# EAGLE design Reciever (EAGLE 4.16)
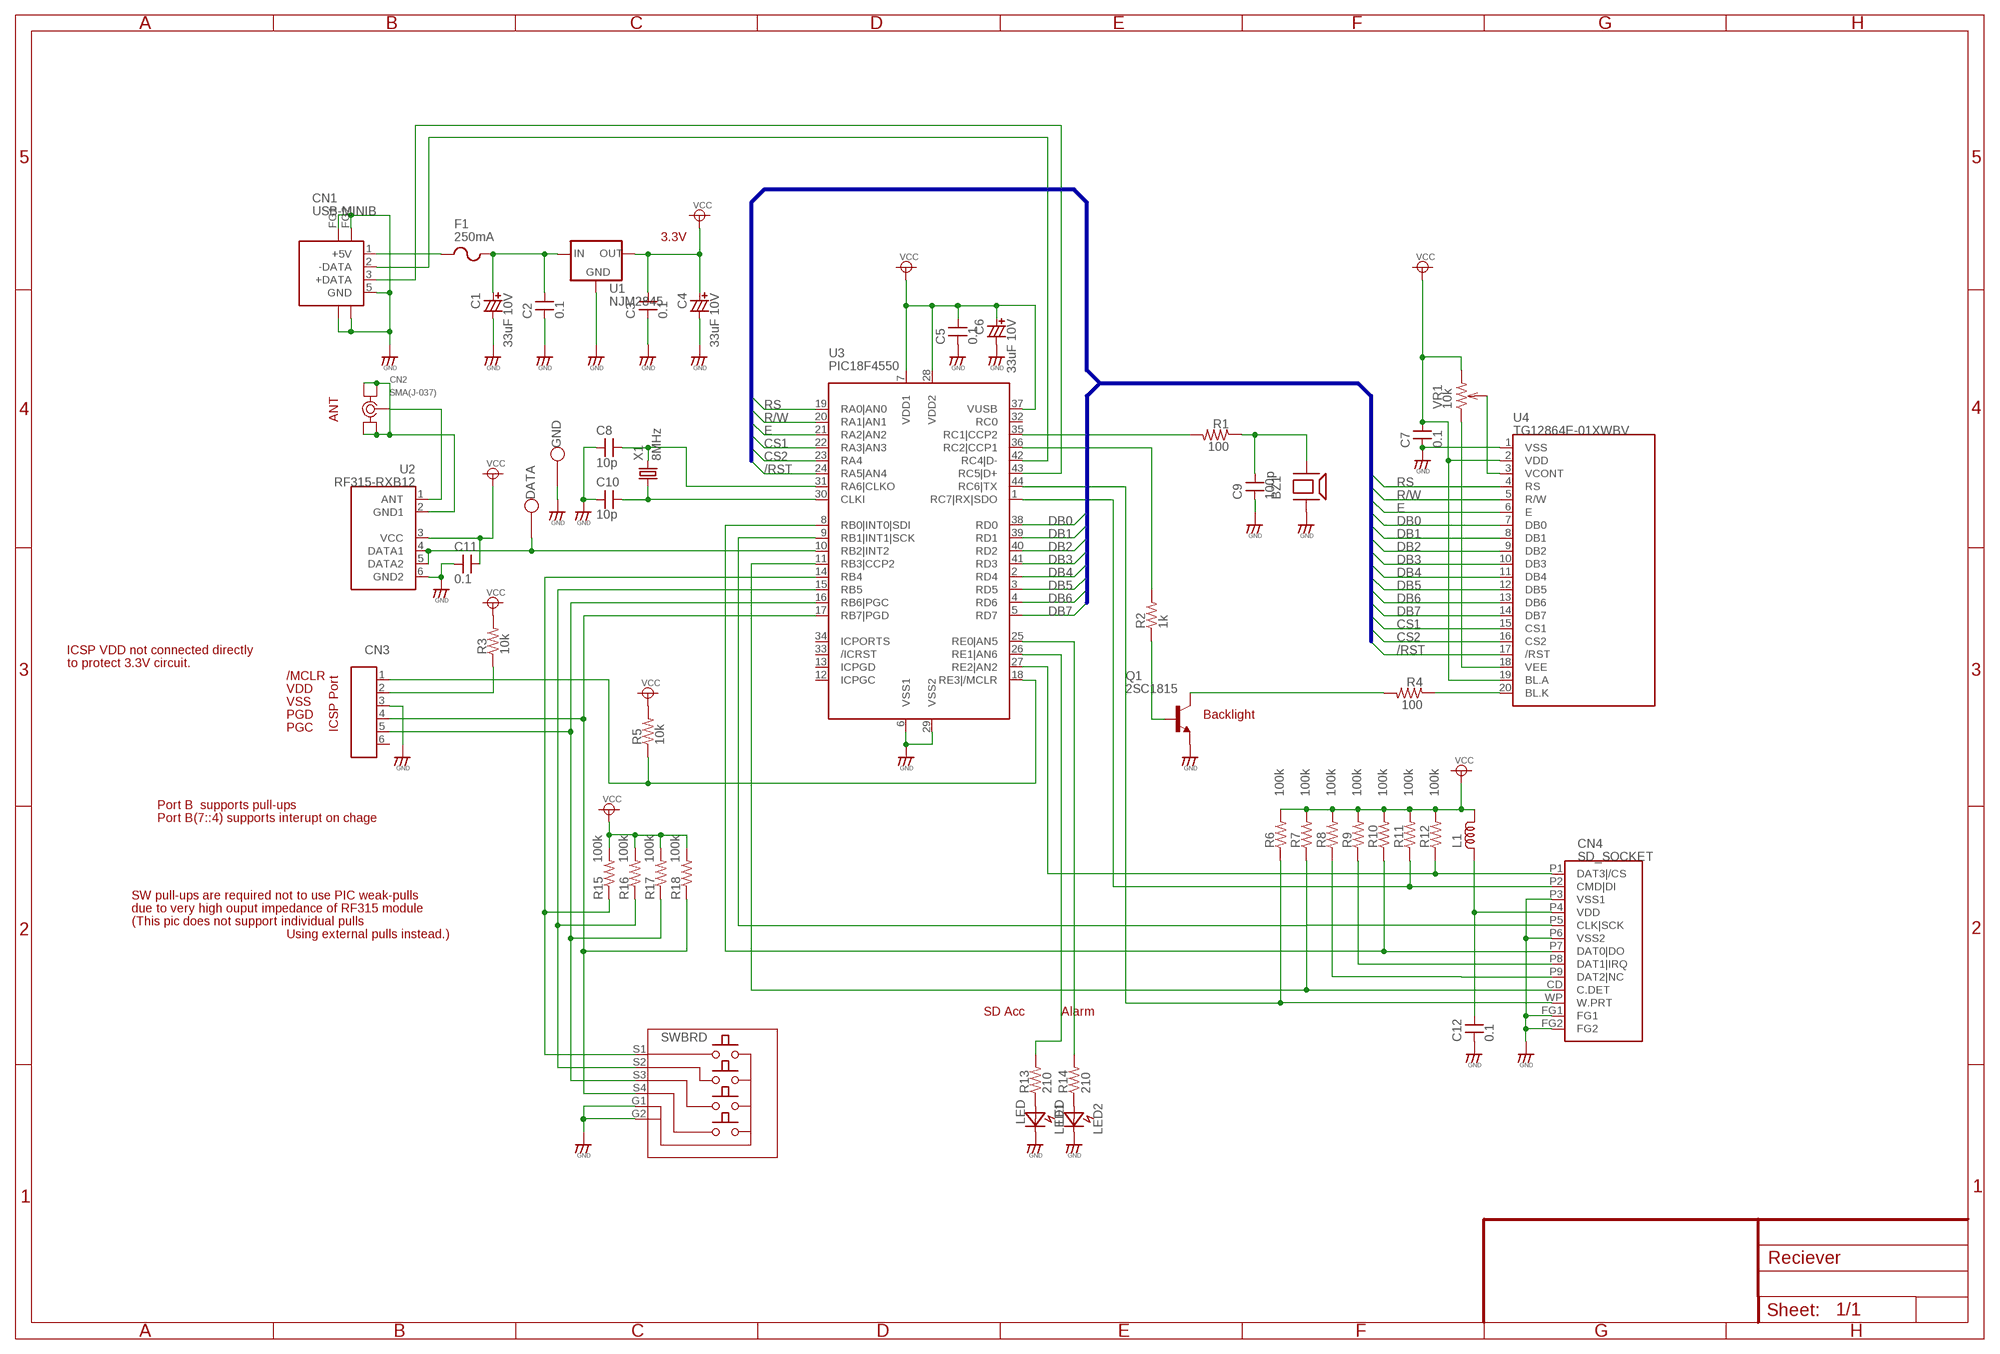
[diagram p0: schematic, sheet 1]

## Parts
BZ1  PIEZO-BZ  [PKM13EPYH4000-A0]
C1  33uF 10V  CCAPSMD3528  [CT3528]
C2  0.1  CAPSM2012  [C2012]
C3  0.1  CAPSM2012  [C2012]
C4  33uF 10V  CCAPSMD3528  [CT3528]
C5  0.1  CAPSM2012  [C2012]
C6  33uF 10V  CCAPSMD3528  [CT3528]
C7  0.1  CAPSM2012  [C2012]
C8  10p  CAPDIP_1  [CAP_DIP_1]
C9  100p  CAPDIP_1  [CAP_DIP_1]
C10  10p  CAPDIP_1  [CAP_DIP_1]
C11  0.1  CAPSM2012  [C2012]
C12  0.1  CAPSM2012  [C2012]
CN1  USB-MINIB  [MINI-USB-B]
CN2  SMA(J-037)  [SMA-J(S-037)]
CN3  CON_6PHDR_L  [CON_HDR_L_SIP6]
CN4  SD_SOCKET  [SD-88]
DATA  TP  [TP]
F1  250mA  POLYSW8X2MM  [AX_08X02_2P_200]
GND  TP  [TP]
L1  MICRO_INDUCTORSMD2012  [L2012C]
LED1  LED  [LED_3MM_VIRT_2]
LED2  LED  [LED_3MM_VIRT_2]
Q1  2SC1815  [TO92]
R1  100  R0.125W_2P  [R_0.125W_2]
R2  1k  RSMD2012  [R2012]
R3  10k  RSMD2012  [R2012]
R4  100  R0.125W_2P  [R_0.125W_2]
R5  10k  RSMD2012  [R2012]
R6  100k  RSMD2012  [R2012]
R7  100k  RSMD2012  [R2012]
R8  100k  RSMD2012  [R2012]
R9  100k  RSMD2012  [R2012]
R10  100k  RSMD2012  [R2012]
R11  100k  RSMD2012  [R2012]
R12  100k  RSMD2012  [R2012]
R13  210  R0.125W_2P  [R_0.125W_2]
R14  210  R0.125W_2P  [R_0.125W_2]
R15  100k  RSMD2012  [R2012]
R16  100k  RSMD2012  [R2012]
R17  100k  RSMD2012  [R2012]
R18  100k  RSMD2012  [R2012]
SWBRD  SW_BOARD  [SW_BOARD]
U1  NJM2845  [TO252]
U2  RF315-RXB12  [RF315-RXB12]
U3  PIC18F4550  [TQFP44]
U4  TG12864E-01XWBV  [TG12864E-01XWBV]
VR1  10k  VR  [VR-7MM]
X1  8MHz  CRYSTALHC49S  [HC49/S]

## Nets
/RST: U3.24(RA5|AN4) U4.17(/RST)
CS1: U3.22(RA3|AN3) U4.15(CS1)
CS2: U3.23(RA4) U4.16(CS2)
DB0: U3.38(RD0) U4.7(DB0)
DB1: U3.39(RD1) U4.8(DB1)
DB2: U3.40(RD2) U4.9(DB2)
DB3: U3.41(RD3) U4.10(DB3)
DB4: U3.2(RD4) U4.11(DB4)
DB5: U3.3(RD5) U4.12(DB5)
DB6: U3.4(RD6) U4.13(DB6)
DB7: U3.5(RD7) U4.14(DB7)
DVCC: C3.2 C4.+ C5.2 C6.+ C7.2 C11.2 L1.2 R3.2 R5.2 R6.2 R7.2 R8.2 R9.2 R10.2 R11.2 R12.2 R15.2 R16.2 R17.2 R18.2 U1.3(OUT) U2.3(VCC) U3.7(VDD1) U3.28(VDD2) U3.37(VUSB) U4.2(VDD) U4.19(BL.A) VR1.3 ; supply symbol labelled VCC
E: U3.21(RA2|AN2) U4.6(E)
GND: BZ1.2 C1.- C2.1 C3.1 C4.- C5.1 C6.- C7.1 C8.1 C9.1 C10.1 C11.1 C12.1 CN1.5(GND) CN1.FG1 CN1.FG2 CN1.FG3 CN1.FG4 CN3.3 CN4.FG1 CN4.FG2 CN4.P3(VSS1) CN4.P6(VSS2) GND.TP LED1.K LED2.K Q1.1(E) SWBRD.G1 SWBRD.G2 U1.2(GND) U2.6(GND2) U3.6(VSS1) U3.29(VSS2) U4.1(VSS)
N$1: CN3.1 R5.1 U3.18(RE3|/MCLR)
N$4: CN1.2(-DATA) U3.42(RC4|D-)
N$5: CN1.3(+DATA) U3.43(RC5|D+)
N$6: R14.2 U3.25(RE0|AN5)
N$8: R2.2 U3.36(RC2|CCP1)
N$9: R4.1 U4.20(BL.K)
N$10: Q1.2(C) R4.2
N$11: DATA.TP U2.4(DATA1) U2.5(DATA2) U3.10(RB2|INT2)
N$12: CN4.P1(DAT3|/CS) R12.1 U3.27(RE2|AN2)
N$13: LED2.A R14.1
N$14: LED1.A R13.1
N$15: CN4.P7(DAT0|DO) R10.1 U3.8(RB0|INT0|SDI)
N$16: CN4.P5(CLK|SCK) U3.9(RB1|INT1|SCK)
N$17: CN4.P2(CMD|DI) R11.1 U3.1(RC7|RX|SDO)
N$18: C1.+ C2.2 F1.2 U1.1(IN)
N$19: CN4.CD(C.DET) R7.1 U3.11(RB3|CCP2)
N$20: CN4.WP(W.PRT) R6.1 U3.44(RC6|TX)
N$21: U4.3(VCONT) VR1.2
N$22: Q1.3(B) R2.1
N$23: CN2.HOT U2.1(ANT)
N$24: C12.2 CN4.P4(VDD) L1.1
N$25: U4.18(VEE) VR1.1
N$27: CN3.2 R3.1
N$28: R13.2 U3.26(RE1|AN6)
N$29: R1.2 U3.35(RC1|CCP2)
N$30: C8.2 U3.31(RA6|CLKO) X1.2
N$31: C10.2 U3.30(CLKI) X1.1
N$32: BZ1.1 C9.2 R1.1
N$33: CN2.G1 CN2.G2 CN2.G3 CN2.G4 U2.2(GND1)
N$34: CN1.1(+5V) F1.1
N$35: R15.1 SWBRD.S1 U3.14(RB4)
N$36: CN4.P8(DAT1|IRQ) R9.1
N$37: CN4.P9(DAT2|NC) R8.1
N$38: R16.1 SWBRD.S2 U3.15(RB5)
N$39: CN3.5 R17.1 SWBRD.S3 U3.16(RB6|PGC)
N$40: CN3.4 R18.1 SWBRD.S4 U3.17(RB7|PGD)
R/W: U3.20(RA1|AN1) U4.5(R/W)
RS: U3.19(RA0|AN0) U4.4(RS)
Unconnected: CN3.6 U3.12(ICPGC) U3.13(ICPGD) U3.32(RC0) U3.33(/ICRST) U3.34(ICPORTS)

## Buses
RS,R/W,E,DB[0..7],CS1,CS2,/RST

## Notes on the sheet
- 3.3V
- ANT
- ICSP VDD not connected directly
- to protect 3.3V circuit.
- /MCLR
- VDD
- VSS
- PGD | Backlight
- PGC | ICSP Port
- Port B  supports pull-ups
- Port B(7::4) supports interupt on chage
- SW pull-ups are required not to use PIC weak-pulls
- due to very high ouput impedance of RF315 module
- (This pic does not support individual pulls
- Using external pulls instead.)
- SD Acc | Alarm

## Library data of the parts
BZ1 = WirelessTemp:PIEZO-BZ
C1 C4 C6 = WirelessTemp:CCAP: Polar capacitor
C2 C3 C5 C7-C12 = WirelessTemp:CAP: Non polar capacitor
CN1 = WirelessTemp:USB-MINIB
CN2 = WirelessTemp:SMA(J-037)
CN3 = WirelessTemp:CON_6P
CN4 = WirelessTemp:SD_SOCKET
DATA GND = WirelessTemp:TP
F1 = WirelessTemp:POLYSW
L1 = WirelessTemp:MICRO_INDUCTOR
LED1 LED2 = WirelessTemp:LED
Q1 = WirelessTemp:2SC1815: General use NPN transistor
R1-R18 = WirelessTemp:R
SWBRD = WirelessTemp:SW_BOARD
U1 = WirelessTemp:NJM2845
U2 = WirelessTemp:RF315-RXB12
U3 = WirelessTemp:PIC18F4550
U4 = WirelessTemp:TG12864E-01XWBV
VR1 = WirelessTemp:VR
X1 = WirelessTemp:CRYSTAL: CRYSTAL

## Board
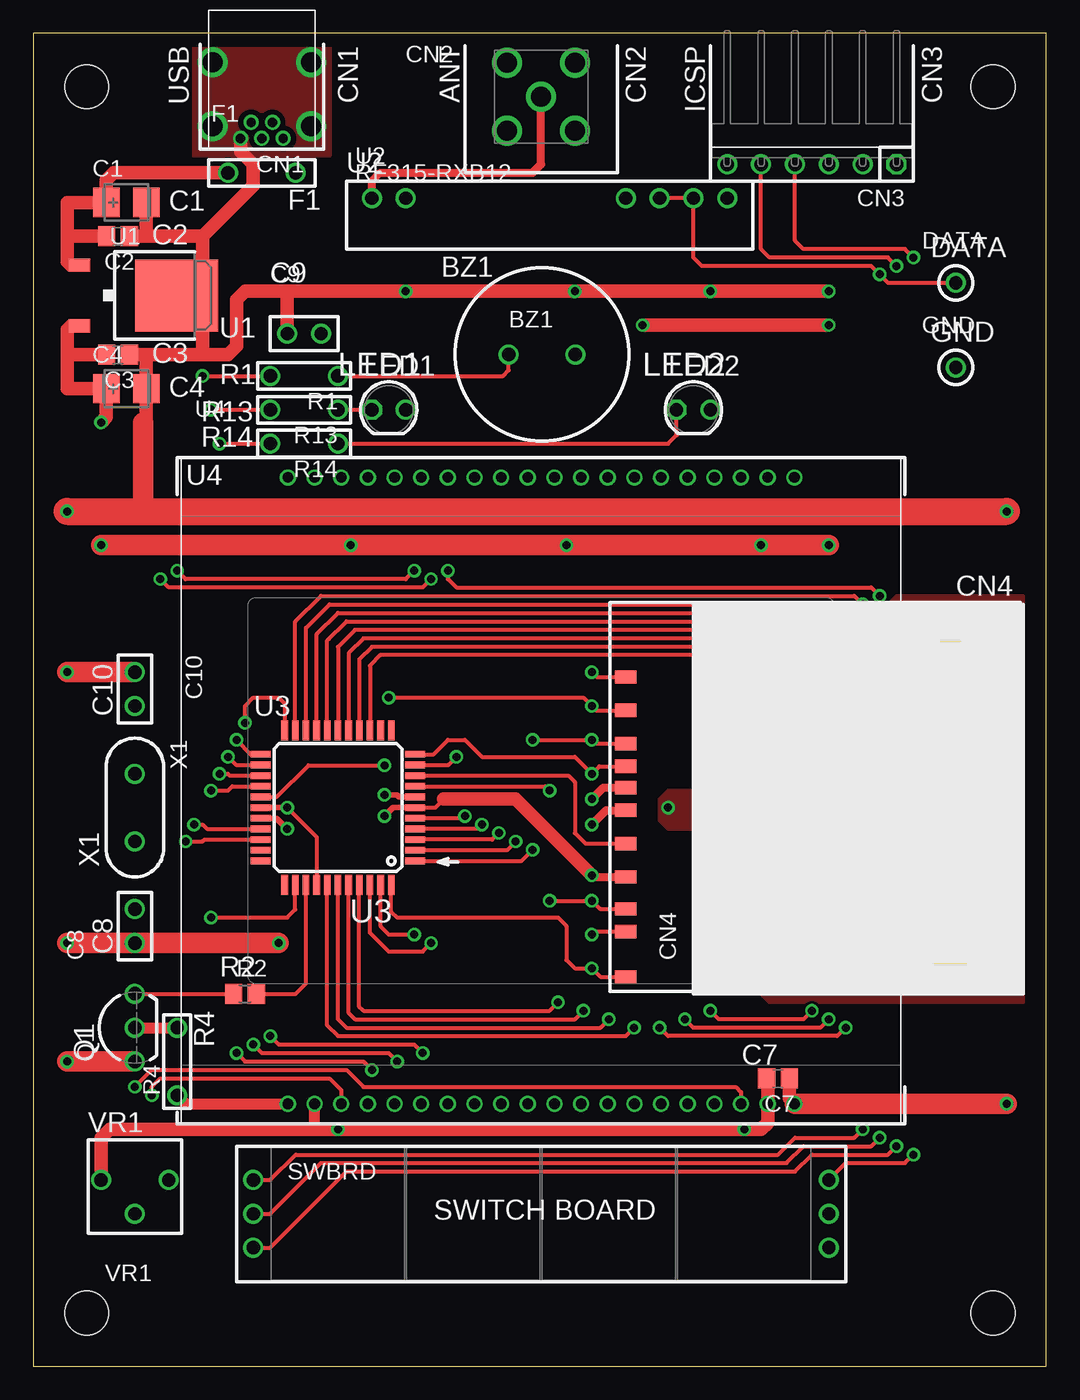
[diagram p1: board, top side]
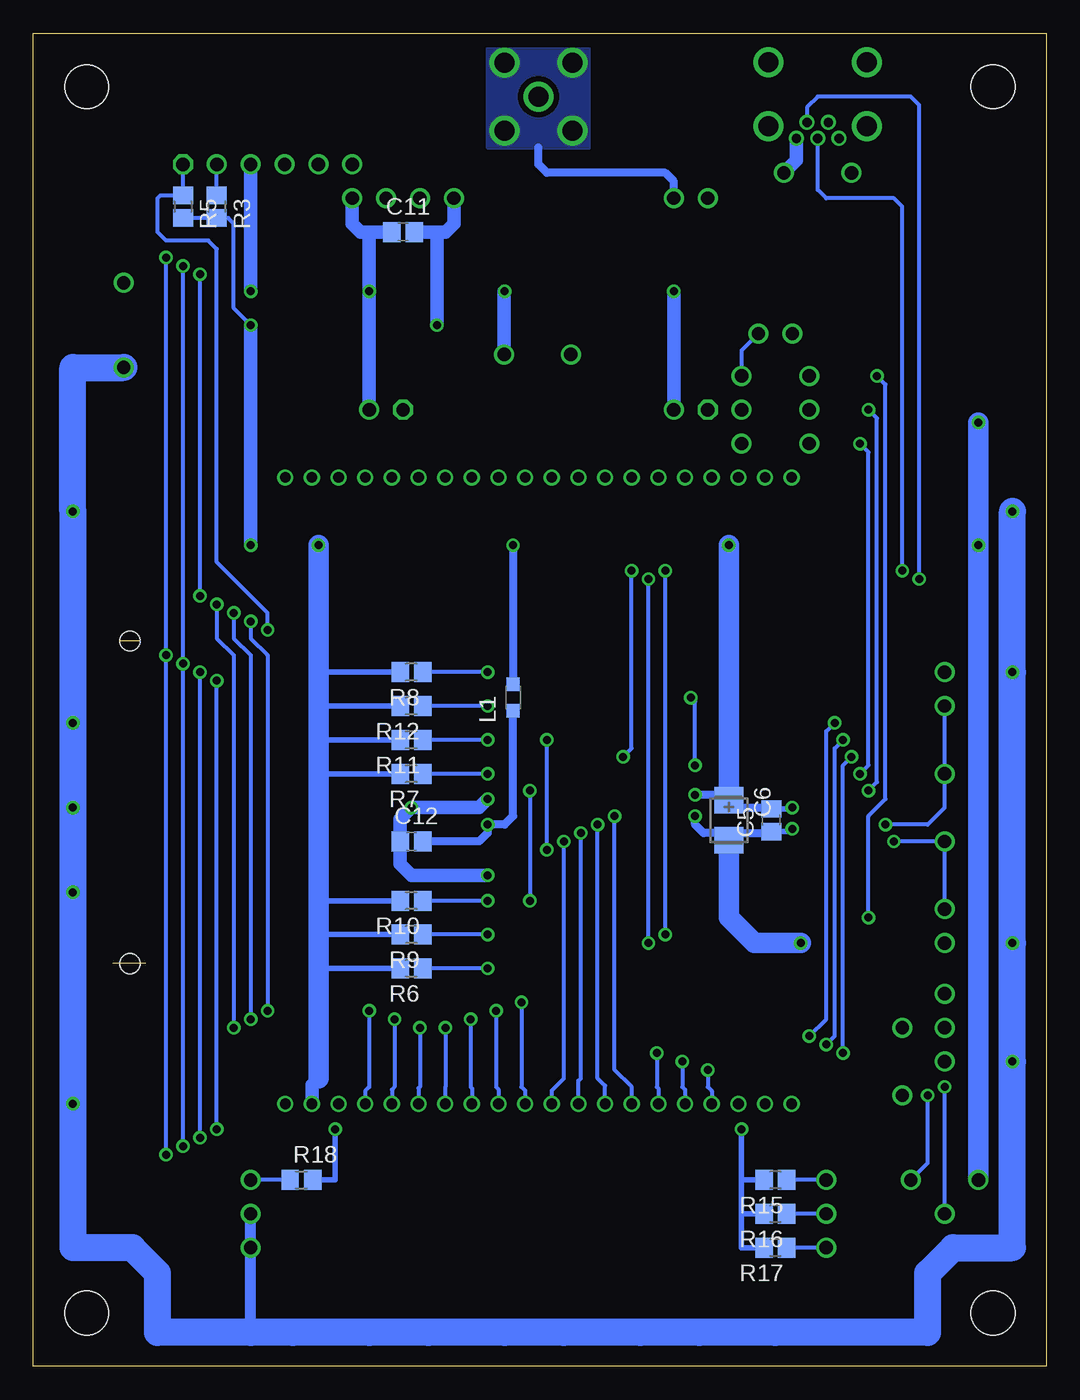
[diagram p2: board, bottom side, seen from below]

Size 76 x 100 mm. Coordinates in mm from the lower left corner, seen from the top.
Outline: 0,0 76,0 76,100 0,100 0,0
Copper layers (1*16): Top 0.035mm / dielectric 1.5mm / Bottom 0.035mm
Design rules "Olimex8mils": minimum track width 8mil, minimum drill 0.6mm, track to track 8mil, track to pad 8mil, pad to pad 8mil, via to via 8mil, smd to smd 8mil, copper to edge 40mil, drill to drill 10mil, minimum pad ring 8mil, minimum via ring 8mil, stop-mask expansion 0mil, vias tented up to drill 0mil, thermal gap 10mil
Holes 3.3 mm at 4,96 72,96 72,4 4,4

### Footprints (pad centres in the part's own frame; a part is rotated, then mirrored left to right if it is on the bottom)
PKM13EPYH4000-A0 = drill 1 round: 1 -2.5,0; 2 2.5,0
CT3528 = smd 2 x 2.2: + -1.5,0; - 1.5,0
C2012 = smd 1.3 x 1.5: 1 -0.85,0; 2 0.85,0
CAP_DIP_1 = drill 1 round: 1 -1.27,0; 2 1.27,0
MINI-USB-B = drill 0.7 pad 1.118 round: 1 -1.6,4.4; 2 -0.8,3.2; 3 0,4.4; 4 0.8,3.2; 5 1.6,4.4 | drill 1.5 round: FG1 -3.7,3.5; FG2 3.7,3.5; FG3 -3.7,-1.3; FG4 3.7,-1.3
SMA-J(S-037) = drill 1.5 round: G1 -2.54,2.54; G2 2.54,2.54; G3 -2.54,-2.54; G4 2.54,-2.54; HOT 0,0
CON_HDR_L_SIP6 = drill 1 octagon: 1 -6.35,0 | drill 1 round: 2 -3.81,0; 3 -1.27,0; 4 1.27,0; 5 3.81,0; 6 6.35,0
SD-88 = smd 1 x 1.6: CD 15.8,0; P1 20,0; P2 17.5,0; P3 14.2,0; P4 12.5,0; P5 10,0; P6 7.5,0; P7 5.1,0; P8 3.4,0; P9 22.5,0; WP 0,0 | smd 1.2 x 1.6: FG1 27.5,-21; FG2 -0.5,-22.2 | hole 1.5: 1,-24.3; 25.2,-24.3
TP = drill 1 round: TP 0,0
AX_08X02_2P_200 = drill 1 round: 1 2.54,0; 2 -2.54,0
L2012C = smd 1 x 1: 1 -1,0; 2 1,0
LED_3MM_VIRT_2 = drill 1 octagon: A -1.27,0 | drill 1 round: K 1.27,0
TO92 = drill 1 round: 1 -2.54,0; 2 0,0; 3 2.54,0
R_0.125W_2 = drill 1 round: 1 -2.54,0; 2 2.54,0
R2012 = smd 1.3 x 1.5: 1 -0.85,0; 2 0.85,0
SW_BOARD = drill 1 round: G1 21.59,0; G2 21.59,-2.54; S1 -21.59,2.54; S2 -21.59,0; S3 -21.59,-2.54; S4 21.59,2.54
TO252 = smd 1 x 1.6: 1 -2.28,-4.8; 3 2.28,-4.8 | smd 5.4 x 6.2: 2 0,2.5
RF315-RXB12 = drill 1 round: 1 -12.7,0; 2 -10.16,0; 3 6.35,0; 4 8.89,0; 5 11.43,0; 6 13.97,0
TQFP44 = smd 1.5 x 0.5: 1 -5.8,4; 2 -5.8,3.2; 3 -5.8,2.4; 4 -5.8,1.6; 5 -5.8,0.8; 6 -5.8,0; 7 -5.8,-0.8; 8 -5.8,-1.6; 9 -5.8,-2.4; 10 -5.8,-3.2; 11 -5.8,-4; 23 5.8,-4; 24 5.8,-3.2; 25 5.8,-2.4; 26 5.8,-1.6; 27 5.8,-0.8; 28 5.8,0; 29 5.8,0.8; 30 5.8,1.6; 31 5.8,2.4; 32 5.8,3.2; 33 5.8,4 | smd 0.5 x 1.5: 12 -4,-5.8; 13 -3.2,-5.8; 14 -2.4,-5.8; 15 -1.6,-5.8; 16 -0.8,-5.8; 17 0,-5.8; 18 0.8,-5.8; 19 1.6,-5.8; 20 2.4,-5.8; 21 3.2,-5.8; 22 4,-5.8; 34 4,5.8; 35 3.2,5.8; 36 2.4,5.8; 37 1.6,5.8; 38 0.8,5.8; 39 0,5.8; 40 -0.8,5.8; 41 -1.6,5.8; 42 -2.4,5.8; 43 -3.2,5.8; 44 -4,5.8
TG12864E-01XWBV = drill 0.8 round: 1 19,-23.5; 2 17,-23.5; 3 15,-23.5; 4 13,-23.5; 5 11,-23.5; 6 9,-23.5; 7 7,-23.5; 8 5,-23.5; 9 3,-23.5; 10 1,-23.5; 11 -1,-23.5; 12 -3,-23.5; 13 -5,-23.5; 14 -7,-23.5; 15 -9,-23.5; 16 -11,-23.5; 17 -13,-23.5; 18 -15,-23.5; 19 -17,-23.5; 20 -19,-23.5; 21 19,23.5; 22 17,23.5; 23 15,23.5; 24 13,23.5; 25 11,23.5; 26 9,23.5; 27 7,23.5; 28 5,23.5; 29 3,23.5; 30 1,23.5; 31 -1,23.5; 32 -3,23.5; 33 -5,23.5; 34 -7,23.5; 35 -9,23.5; 36 -11,23.5; 37 -13,23.5; 38 -15,23.5; 39 -17,23.5; 40 -19,23.5
VR-7MM = drill 1 round: 1 -2.54,0; 2 0,2.54; 3 2.54,0
HC49/S = drill 1 round: 1 -2.54,0; 2 2.54,0

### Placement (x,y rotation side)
BZ1  38.16,75.91 0 top
C1  6.99,87.31 0 top
C2  6.35,84.77 180 top
C3  6.35,75.88 180 top
C4  6.99,73.34 0 top
C5  20.64,40.96 90 bottom
C6  23.81,40.96 270 bottom
C7  55.88,21.59 180 top
C8  7.62,33.02 90 top
C9  20.32,77.47 0 top
C10  7.62,50.8 270 top
C11  48.26,85.09 0 bottom
C12  47.62,39.37 0 bottom
CN1  17.14,96.52 180 top
CN2  38.1,95.25 0 top
CN3  58.42,90.17 180 top
CN4  44.45,29.21 90 top
DATA  69.22,81.28 0 top
F1  17.14,89.53 0 top
GND  69.22,74.93 0 top
L1  40.01,50.16 90 bottom
LED1  26.67,71.75 0 top
LED2  49.53,71.75 0 top
Q1  7.62,25.4 90 top
R1  20.32,74.3 180 top
R2  15.88,27.94 0 top
R3  62.23,87 270 bottom
R4  10.79,22.86 90 top
R5  64.77,87 270 bottom
R6  47.62,29.84 180 bottom
R7  47.62,44.45 180 bottom
R8  47.62,52.07 180 bottom
R9  47.62,32.38 180 bottom
R10  47.62,34.92 180 bottom
R11  47.62,46.99 180 bottom
R12  47.62,49.53 180 bottom
R13  20.32,71.75 180 top
R14  20.32,69.22 180 top
R15  20.32,13.97 180 bottom
R16  20.32,11.43 180 bottom
R17  20.32,8.89 180 bottom
R18  55.88,13.97 0 bottom
SWBRD  38.1,11.43 0 top
U1  8.26,80.33 270 top
U2  38.1,87.63 0 top
U3  22.86,41.91 180 top
U4  38.1,43.18 0 top
VR1  7.62,13.97 180 top
X1  7.62,41.91 270 top

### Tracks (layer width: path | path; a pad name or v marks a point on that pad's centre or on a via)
/RST  (via drill 0.6)
  Top 0.305: v15.24,23.5 15.88,22.86 24.77,22.86 v25.4,22.23 | U3.24 15.21,45.11 v14.61,45.72
  Bottom 0.305: v15.24,23.5 15.24,45.09 v14.61,45.72 | v25.4,22.23 25.4,20.95 25.1,20.66 U4.17
CS1  (via drill 0.6)
  Top 0.305: U3.22 18.86,49.72 18.41,50.16 16.51,50.16 15.88,49.53 v15.88,48.26 | v17.78,24.77 18.41,24.13 28.57,24.13 v29.21,23.5
  Bottom 0.305: v17.78,24.77 16.51,26.04 16.51,47.62 v15.88,48.26 | v29.21,23.5 29.21,20.95 29.1,20.84 U4.15
CS2  (via drill 0.6)
  Top 0.305: v16.51,24.13 17.14,23.5 26.67,23.5 v27.3,22.86 | U3.23 16.32,45.91 v15.24,46.99
  Bottom 0.305: v16.51,24.13 15.88,24.77 15.88,46.35 v15.24,46.99 | v27.3,22.86 27.3,20.95 27.1,20.75 U4.16
DB0  (via drill 0.6)
  Top 0.305: v45.09,25.4 44.45,24.77 22.86,24.77 22.06,25.57 U3.38
  Bottom 0.305: v45.09,25.4 45.09,20.95 45.1,20.94 U4.7
DB1  (via drill 0.6)
  Top 0.305: v43.18,26.04 42.55,25.4 23.5,25.4 22.86,26.04 U3.39
  Bottom 0.305: v43.18,26.04 43.18,20.95 43.1,20.88 U4.8
DB2  (via drill 0.6)
  Top 0.305: v41.27,26.67 40.64,26.04 24.13,26.04 23.66,26.5 U3.40
  Bottom 0.305: v41.27,26.67 41.27,20.95 41.1,20.78 U4.9
DB3  (via drill 0.6)
  Top 0.305: v39.37,27.3 38.73,26.67 24.77,26.67 24.46,26.98 U3.41
  Bottom 0.305: v39.37,27.3 39.37,20.95 39.1,20.68 U4.10
DB4  (via drill 0.6)
  Top 0.305: U3.2 35.53,38.71 v36.2,39.37
  Bottom 0.305: v36.2,39.37 36.2,21.59 37.1,20.68 U4.11
DB5  (via drill 0.6)
  Top 0.305: U3.3 34.43,39.51 v34.92,40.01
  Bottom 0.305: v34.92,40.01 34.92,21.59 35.1,21.41 U4.12
DB6  (via drill 0.6)
  Top 0.305: U3.4 33.33,40.31 v33.66,40.64
  Bottom 0.305: v33.66,40.64 33.66,21.59 33.1,21.04 U4.13
DB7  (via drill 0.6)
  Top 0.305: U3.5 32.22,41.11 v32.38,41.27
  Bottom 0.305: v32.38,41.27 32.38,22.23 31.1,20.94 U4.14
DVCC  (via drill 0.6)
  Top 0.305: U3.37 21.26,39.7 v19.05,41.91
  Top 0.406: v19.05,41.91 U3.28 | U3.7 27.46,42.71 27.3,42.86 v26.35,42.86 | C7.2 55.24,21.59 55.1,21.45 | 20.95,17.78 21.1,17.93
  Top 0.813: 21.1,17.93 U4.19
  Top 1.016: 2.54,75.88 2.54,77.79 2.8,78.05 U1.3 | 2.54,75.88 2.54,73.34 C4.+ 5.49,71.21 v5.08,70.8 | 2.54,75.88 C3.2 | 55.1,21.45 U4.2 55.1,18.27 54.61,17.78 v53.34,17.78 v22.86,17.78 20.95,17.78 5.71,17.78 5.08,17.14 VR1.3 | v59.69,78.11 v45.72,78.11
  Top 1.524: v5.08,61.59 v23.81,61.59 v40.01,61.59 v54.61,61.59 v59.69,61.59
  Bottom 0.305: R5.2 R3.2 61.38,86.14 60.96,85.72 60.96,79.38 v59.69,78.11
  Bottom 0.406: C5.2 19.15,41.81 v19.05,41.91 | 54.61,29.84 R6.2 | 54.61,52.07 R8.2 | 54.61,49.53 R12.2 | 54.61,46.99 R11.2 | 54.61,44.45 R7.2 | 54.61,34.92 R10.2 | 54.61,32.38 R9.2 | 22.86,13.97 R15.2 | 22.86,11.43 R16.2 | 22.86,11.43 22.86,8.89 R17.2 | 22.86,13.97 22.86,11.43 | v22.86,17.78 22.86,13.97 | R18.2 53.34,13.97 v53.34,17.78
  Bottom 0.61: v40.01,61.59 L1.2 | v26.35,42.86 24.22,42.86 C6.+ 23.27,41.91 20.74,41.91
  Bottom 0.813: 20.74,41.91 C5.2
  Bottom 1.016: U4.2 55.1,21.1 54.61,21.59 | 45.72,85.09 45.09,85.09 44.45,85.72 U2.3 | 45.72,85.09 C11.2 | v59.69,61.59 v59.69,78.11 | v45.72,78.11 45.72,85.09
  Bottom 1.524: v54.61,61.59 54.61,52.07 54.61,49.53 54.61,46.99 54.61,44.45 54.61,34.92 54.61,32.38 54.61,29.84 54.61,21.59 | v23.81,61.59 C6.+ | VR1.3 v5.08,61.59 v5.08,70.8
E  (via drill 0.6)
  Top 0.305: U3.21 19.66,55.85 21.59,57.78 61.59,57.78 v62.23,57.15 | v60.96,25.4 60.33,24.77 47.62,24.77 v46.99,25.4
  Bottom 0.305: v62.23,57.15 62.23,54.61 60.96,53.34 v60.96,25.4 | v46.99,25.4 46.99,20.95 47.1,20.84 U4.6
GND  (via drill 0.6)
  Top 0.305: 28.57,41.91 30.16,41.91 30.8,42.55
  Top 0.406: U3.29 18.26,41.11 v19.05,40.32 | U3.6 28.57,41.91 26.99,41.91 v26.35,41.27 | 12.7,80.33 U1.2
  Top 0.61: CN4.P3 42.77,43.41 v41.91,42.55 | CN4.P6 42.03,36.71 v41.91,36.83
  Top 0.813: 8.26,70.8 8.48,71.03
  Top 1.016: U4.1 57.15,19.68 56.73,20.11 C7.1 | 12.7,84.77 12.7,80.33 12.7,75.88 | 12.7,84.77 8.26,84.77 | 8.26,84.77 C2.1 | 8.26,75.88 C3.1 | 8.26,75.88 12.7,75.88 | 12.7,75.88 14.61,75.88 15.24,76.52 15.24,80.01 15.88,80.64 19.05,80.64 | 8.26,75.88 8.48,75.65 C4.- 8.48,71.03 | C1.- 8.48,85 8.26,84.77 | v41.91,36.83 36.2,42.55 30.8,42.55 | 19.05,80.64 v27.94,80.64 v40.64,80.64 v50.8,80.64 v59.69,80.64 | 19.05,80.64 C9.1 | CN1.5 15.54,91.14 16.51,90.17 16.51,88.58 12.7,84.77
  Top 1.524: v2.54,22.86 Q1.1 | v2.54,52.07 C10.1 | v73.03,19.68 57.15,19.68 | v18.41,31.75 C8.1 v2.54,31.75 | 8.26,64.14 8.26,70.8
  Top 2.032: v2.54,64.14 8.26,64.14 v73.03,64.14
  Bottom 0.305: 20.32,2.54 19.86,3 | 26.04,2.54 25.86,2.71 | 30.48,2.54 30.02,3 | 36.2,2.54 36.02,2.71 | 40.64,2.54 40.18,3 | 46.35,2.54 46.18,2.71 | 50.8,2.54 50.34,3 | 56.52,2.54 56.34,2.71
  Bottom 0.406: C5.1 19.27,40.11 v19.05,40.32
  Bottom 0.61: C6.- 23.27,40.01 | 23.27,40.01 20.74,40.01 | v26.35,41.27 26.35,40.64 25.72,40.01 23.27,40.01
  Bottom 0.813: 20.74,40.01 C5.1 | SWBRD.G1 SWBRD.G2 59.69,2.54
  Bottom 1.016: v41.91,36.83 47.62,36.83 48.48,37.68 C12.1 48.48,41.06 v47.62,41.91 42.55,41.91 v41.91,42.55 | v27.94,80.64 LED1.K | LED2.K v50.8,80.64 50.8,85.09 | 50.8,85.09 C11.1 | 50.8,85.09 51.44,85.09 52.07,85.72 U2.6 | v59.69,80.64 CN3.3 | BZ1.2 40.66,80.62 v40.64,80.64
  Bottom 1.524: v18.41,31.75 21.91,31.75 23.81,33.66 C6.-
  Bottom 2.032: v2.54,64.14 v2.54,52.07 v2.54,31.75 v2.54,22.86 2.54,8.89 6.99,8.89 8.89,6.99 8.89,2.54 20.32,2.54 26.04,2.54 30.48,2.54 36.2,2.54 40.64,2.54 46.35,2.54 50.8,2.54 56.52,2.54 59.69,2.54 66.67,2.54 66.67,6.99 68.58,8.89 73.03,8.89 v73.03,19.68 v73.03,35.56 v73.03,41.91 v73.03,48.26 v73.03,64.14 73.03,74.93 GND.TP
  pour Top (no thermals): 74.3,57.78 64.77,57.78 64.14,57.15 64.14,55.24 64.77,54.61 66.04,54.61 66.67,53.98 66.67,52.7 64.77,50.8 55.24,50.8 54.61,50.16 54.61,43.18 47.62,43.18 46.99,42.55 46.99,40.96 47.62,40.32 54.61,40.32 54.61,27.94 55.24,27.3 74.3,27.3
  pour Top (isolate 0.406, no thermals): 12.06,99.06 22.23,99.06 22.23,90.81 12.06,90.81
N$1  (via drill 0.6)
  Top 0.305: U3.18 22.06,54.45 | 22.06,54.45 22.23,54.61 | 22.06,54.45 23.5,55.88 57.78,55.88 v58.42,55.24
  Bottom 0.305: v58.42,55.24 58.42,56.52 62.23,60.33 62.23,83.82 62.87,84.45 66.04,84.45 66.67,85.09 66.67,87.63 66.46,87.84 R5.1 CN3.1
N$4  (via drill 0.6)
  Top 0.305: U3.42 25.26,32.52 26.67,31.11 29.21,31.11 v29.84,31.75 | v29.84,59.05 29.21,58.42 10.16,58.42 v9.53,59.05
  Bottom 0.305: v29.84,31.75 v29.84,59.05 | v9.53,59.05 9.53,94.61 10.16,95.25 17.14,95.25 17.95,94.45 CN1.2
N$5  (via drill 0.6)
  Top 0.305: U3.43 26.06,32.99 26.67,32.38 v28.57,32.38 | v28.57,59.69 27.94,59.05 11.43,59.05 v10.79,59.69
  Bottom 0.305: v28.57,32.38 v28.57,59.69 | v10.79,59.69 10.79,87 11.43,87.63 16.51,87.63 17.14,88.27 CN1.3
N$6  (via drill 0.6)
  Top 0.305: U3.25 14.74,44.31 14.61,44.45 v13.97,44.45 | v13.97,69.22 R14.2
  Bottom 0.305: v13.97,44.45 13.34,45.09 13.34,68.58 v13.97,69.22
N$8
  Top 0.305: R2.2 19.68,27.94 20.46,28.71 U3.36
N$9
  Top 0.305: U4.20
  Top 0.813: R4.1 11.43,19.68 U4.20
N$10
  Top 0.813: Q1.2 R4.2
N$11  (via drill 0.6)
  Top 0.305: U3.10 31.14,45.11 v31.75,45.72 | v31.11,59.69 31.11,59.05 31.75,58.42 62.87,58.42 v63.5,57.78 | U2.4 U2.5 49.53,83.19 50.16,82.55 62.87,82.55 v63.5,81.92 64.14,81.28 DATA.TP
  Bottom 0.305: v63.5,57.78 v63.5,81.92 | v31.75,45.72 31.11,46.35 v31.11,59.69
N$12  (via drill 0.6)
  Top 0.305: CN4.P1 42.23,49.21 v41.91,49.53 41.27,50.16 v26.67,50.16 | U3.27 18.26,42.71 20.64,45.09 v26.35,45.09
  Bottom 0.305: v41.91,49.53 R12.1 | v26.35,45.09 26.35,49.85 v26.67,50.16
N$13
  Top 0.305: R14.1 47.62,69.22 48.26,69.85 LED2.A
N$14
  Top 0.305: R13.1 LED1.A
N$15  (via drill 0.6)
  Top 0.305: CN4.P7 42.52,34.31 v41.91,34.92 v38.73,34.92 | U3.8 38.41,43.51 v38.73,43.18
  Bottom 0.305: v41.91,34.92 R10.1 | v38.73,43.18 v38.73,34.92
N$16
  Top 0.305: CN4.P5 41.44,39.21 40.64,40.01 40.64,43.81 40.15,44.31 U3.9
N$17  (via drill 0.6)
  Top 0.305: CN4.P2 42.19,46.71 v41.91,46.99 v37.47,46.99 | U3.1 36.64,37.91 v37.47,38.73
  Bottom 0.305: v37.47,38.73 v37.47,46.99 | v41.91,46.99 R11.1
N$18
  Top 1.016: 2.54,84.77 2.54,82.87 2.8,82.61 U1.1 | 2.54,84.77 2.54,87.31 C1.+ 5.49,88.99 6.03,89.53 F1.2 | 2.54,84.77 C2.2
N$19  (via drill 0.6)
  Top 0.305: CN4.CD 42.47,45.01 v41.91,44.45 40.64,45.72 33.66,45.72 32.38,46.99 31.11,46.99 30.04,45.91 U3.11
  Bottom 0.305: v41.91,44.45 R7.1
N$20  (via drill 0.6)
  Top 0.305: CN4.WP 42.55,29.21 v41.91,29.84 40.64,29.84 40.01,30.48 40.01,33.02 39.37,33.66 27.3,33.66 26.86,34.1 U3.44
  Bottom 0.305: v41.91,29.84 R6.1
N$21  (via drill 0.6)
  Top 0.305: U4.3 53.1,20.56 52.7,20.95 24.77,20.95 23.5,22.23 8.89,22.23 v7.62,20.95
  Bottom 0.305: VR1.2 v7.62,20.95
N$22
  Top 0.305: Q1.3 R2.1
N$23
  Top 0.61: U2.1 25.4,88.9 26.04,89.53 37.47,89.53 38.1,90.17 CN2.HOT
N$24  (via drill 0.6)
  Top 0.61: CN4.P4 42.98,41.71 v41.91,40.64
  Bottom 0.61: C12.2 42.55,39.37 41.91,40.01 v41.91,40.64 40.64,40.64 40.01,41.27 L1.1
N$25  (via drill 0.6)
  Top 0.305: U4.18 23.1,20.71 22.23,21.59 9.53,21.59 8.89,20.95 v8.89,20.32
  Bottom 0.305: v8.89,20.32 8.89,15.24 VR1.1
N$27
  Bottom 0.305: R3.1 CN3.2
N$28  (via drill 0.6)
  Top 0.305: U3.26 14.94,43.51 14.61,43.18 v13.34,43.18 | v13.34,71.75 R13.2
  Bottom 0.305: v13.34,43.18 12.7,43.81 12.7,71.12 v13.34,71.75
N$29  (via drill 0.6)
  Top 0.305: v13.34,33.66 19.05,33.66 19.66,34.27 U3.35 | v12.7,74.3 R1.2
  Bottom 0.305: v12.7,74.3 12.06,73.66 12.06,42.55 13.34,41.27 v13.34,33.66
N$30  (via drill 0.6)
  Top 0.305: U3.31 12.84,39.51 12.7,39.37 v11.43,39.37
  Bottom 0.305: C8.2 X1.2 v11.43,39.37
N$31  (via drill 0.6)
  Top 0.305: U3.30 13.03,40.31 12.7,40.64 v12.06,40.64
  Bottom 0.305: C10.2 X1.1 7.62,41.91 8.89,40.64 v12.06,40.64
N$32
  Top 0.305: R1.1 35.24,74.3 35.66,74.72 BZ1.1
  Bottom 0.305: R1.1 22.86,76.2 C9.2
N$33
  Bottom 0.61: U2.2 27.94,88.9 28.57,89.53 37.47,89.53 38.1,90.17 38.1,91.44
  pour Bottom (isolate 0.406, no thermals): 34.29,99.06 41.91,99.06 41.91,91.44 34.29,91.44
N$34
  Bottom 1.016: CN1.1 18.75,90.47 F1.1
N$35  (via drill 0.6)
  Top 0.305: U3.14 25.26,52.56 26.04,53.34 54.61,53.34 55.88,52.07 61.59,52.07 v62.23,51.44 | SWBRD.S1 17.78,13.97 19.68,15.88 55.88,15.88 57.15,17.14 61.59,17.14 v62.23,17.78
  Bottom 0.305: v62.23,17.78 v62.23,51.44 | SWBRD.S1 R15.1
N$36  (via drill 0.6)
  Top 0.305: CN4.P8 42.13,32.61 v41.91,32.38
  Bottom 0.305: v41.91,32.38 R9.1
N$37  (via drill 0.6)
  Top 0.305: CN4.P9 42.27,51.71 v41.91,52.07
  Bottom 0.305: v41.91,52.07 R8.1
N$38  (via drill 0.6)
  Top 0.305: U3.15 24.46,53.03 25.4,53.98 55.24,53.98 56.52,52.7 62.87,52.7 v63.5,52.07 | SWBRD.S2 17.78,11.43 21.59,15.24 56.52,15.24 57.78,16.51 62.87,16.51 v63.5,17.14
  Bottom 0.305: v63.5,17.14 v63.5,52.07 | SWBRD.S2 R16.1
N$39  (via drill 0.6)
  Top 0.305: U3.16 23.66,53.51 24.77,54.61 55.88,54.61 57.15,53.34 64.14,53.34 v64.77,52.7 | SWBRD.S3 17.78,8.89 23.5,14.61 57.15,14.61 58.42,15.88 64.14,15.88 v64.77,16.51 | v64.77,82.55 64.14,83.19 55.24,83.19 54.61,83.82 CN3.5
  Bottom 0.305: v64.77,82.55 v64.77,52.7 v64.77,16.51 | SWBRD.S3 R17.1
N$40  (via drill 0.6)
  Top 0.305: U3.17 22.86,53.98 24.13,55.24 56.52,55.24 57.78,53.98 65.41,53.98 v66.04,53.34 | SWBRD.S4 60.96,15.24 65.41,15.24 v66.04,15.88 | v66.04,83.19 65.41,83.82 57.78,83.82 57.15,84.45 CN3.4
  Bottom 0.305: v66.04,83.19 v66.04,53.34 v66.04,15.88 | R18.1 SWBRD.S4
R/W  (via drill 0.6)
  Top 0.305: U3.20 20.46,55.38 22.23,57.15 60.33,57.15 v60.96,56.52 | v59.69,26.04 59.05,25.4 49.53,25.4 v48.9,26.04
  Bottom 0.305: v60.96,56.52 60.96,54.61 59.69,53.34 v59.69,26.04 | v48.9,26.04 48.9,20.95 49.1,20.75 U4.5
RS  (via drill 0.6)
  Top 0.305: U3.19 21.26,54.91 22.86,56.52 59.05,56.52 v59.69,55.88 | v58.42,26.67 57.78,26.04 51.44,26.04 v50.8,26.67
  Bottom 0.305: v59.69,55.88 59.69,54.61 58.42,53.34 v58.42,26.67 | v50.8,26.67 50.8,20.95 51.1,20.66 U4.4

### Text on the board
Document: Chassis 'EAR' area | ANT | 8 | 8 | 8 | 8 | USB | ICSP | 100 | SD CARD | 76
_tPlace: BZ1
_tNames: USB | CN1 | ANT | CN2 | ICSP | CN3 | U2 | F1 | C1 | C2 | DATA | C9 | U1 | GND | C3 | R1 | LED1 | LED2 | C4 | R13 | R14 | U4 | CN4 | C10 | U3 | X1 | C8 | R2 | R4 | C7 | Q1 | VR1 | SWITCH BOARD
